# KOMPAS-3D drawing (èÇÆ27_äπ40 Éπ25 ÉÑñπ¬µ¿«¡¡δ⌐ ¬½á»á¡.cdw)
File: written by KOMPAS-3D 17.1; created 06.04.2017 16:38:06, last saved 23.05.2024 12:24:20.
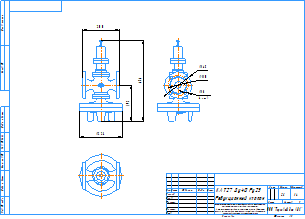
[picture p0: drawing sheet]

Sheet 1: A3, landscape

Title block, sheet 1: name: КАТ27 Ду40 Ру25 / Редукционный клапан; material: Сталь 20  ГОСТ 1050-88; mass: 26; sheets: 1; sheet format: A3; stored path: C:\Users\kka\KOMPAS_Work\!Trash\Редукционный клапан GP-2000\KOMPAS 2D\GP-2000 _ Ду40 Ру25 Редукционный клапан.cdw

Views: Вид 1
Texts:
  Klimkovich
  ADL
  Рама для чертежей
  Лит-Масса-Масштаб
  Материал-Предприятие
  Масштаб
  Изм.
  Лист
  № докум.
  Подп.
  Дата
  Лит.
  Разраб.
  Пров.
  Т.контр.
  Листов
  Внимание! Данный продукт является объектом авторского права ООО «Торговый Дом АДЛ».
  Запрещается изменение, копирование, распространение
  (в том числе путем копирования на другие сайты и ресурсы в Интернете)
  или любое иное использование информации и объектов без предварительного
  согласия правообладателя (ООО «Торговый Дом АДЛ»).
  Н.контр.
  Утв.
  ООО "Торговый дом АДЛ"
  Изменение
  Номер документа
  Подпись
  Обозначение документа
  Наименование изделия
  Масса изделия по ГОСТ 2.109-73
  Порядковый номер листа
  Общее количество листов в документе
  Характер работы, выполненной лицом, подписавшим документ
  Наименование или индекс предприятия, выпускающего документ
  Инв. № подл.
  Подп. и дата
  Взам. инв. №
  Инв. № дубл.
  Инвентарный номер подлинника по ГОСТ 2.501-68
  Подпись принявшего подлинник в отдел технической документации
  Инвентарный номер подлинника, взамен которого выпущен данный подлинник
  Инвентарный номер дубликата по ГОСТ 2.502-68
  Подпись принявшего дубликат в отдел технической документации
  Справ. №
  Перв. примен.
  Обозначение документа, взамен или на основании которого выпущен данный документ
  Обозначение документа, в котором впервые записан данный документ
  Подпись лица, копировавшего чертеж
  Обозначение формата листа
  !Рама для чертежа
Dimensions and other numbers on the sheet: 200; 192; 434; 226; 145; 110; 18; 4 отв.; 1:4; 1; 26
